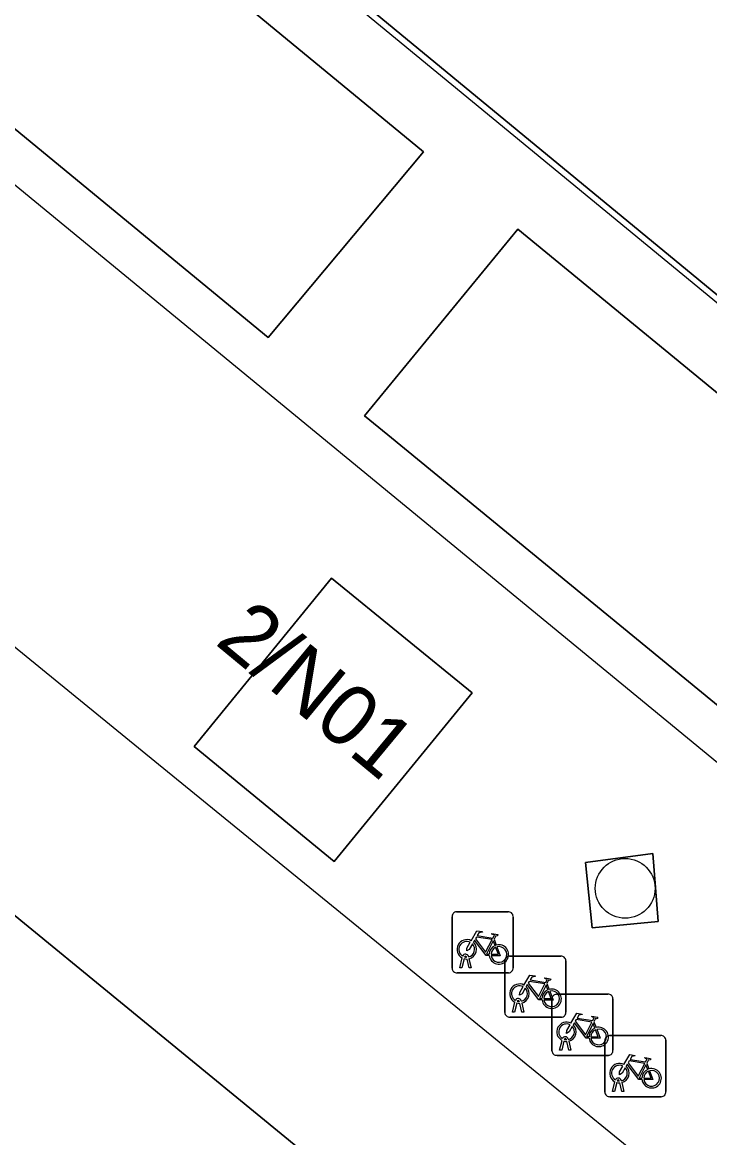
# Model space of a CAD drawing. Extents: x 161772 to 163126, y 383092 to 383917.
# Drawn here: x 161985.95 to 161997.2, y 383240.11 to 383258.37 of the extents above; entities that cross this region are included whole.
import ezdxf

# ---------------------------------------------------------------- set-up
doc = ezdxf.new("R2010")
doc.units = 0
for name, color, linetype in [('IMGEO_Boom', 7, 'Continuous'), ('IMGEO_Fietsenrek', 7, 'Continuous'), ('IMGEO_Groenvoorziening', 7, 'Continuous'), ('IMGEO_Lijnafwatering', 7, 'Continuous'), ('IMGEO_Pand', 7, 'Continuous'), ('IMGEO_Pand_nummerreeks', 7, 'Continuous'), ('IMGEO_Parkeervlak_gesloten', 7, 'Continuous'), ('IMGEO_Rijbaan_lokaal_open', 7, 'Continuous')]:
    doc.layers.add(name, color=color, linetype=linetype)

msp = doc.modelspace()

# ---------------------------------------------------------------- linework, layer by layer
at = {"layer": 'IMGEO_Boom'}
msp.add_circle((161995.818, 383244.188), 0.489, dxfattribs=at)
at = {"layer": 'IMGEO_Fietsenrek'}
for p, q in [((161993.059, 383243.805), (161993.9, 383243.805)), ((161993.9, 383243.805), (161993.059, 383243.805)), ((161993.984, 383243.73), (161993.984, 383242.889)), ((161993.984, 383242.889), (161993.984, 383243.73)), ((161992.984, 383242.88), (161992.984, 383243.721)), ((161992.984, 383243.721), (161992.984, 383242.88)), ((161993.671, 383243.354), (161993.707, 383243.259)), ((161993.111, 383242.889), (161993.15, 383243.049)), ((161993.18, 383243.037), (161993.145, 383242.889)), ((161993.222, 383243.061), (161993.221, 383243.065)), ((161993.263, 383242.889), (161993.229, 383243.031)), ((161993.253, 383243.072), (161993.254, 383243.065)), ((161993.261, 383243.035), (161993.296, 383242.889)), ((161993.923, 383243.079), (161994.764, 383243.079)), ((161994.764, 383243.079), (161993.923, 383243.079)), ((161994.848, 383243.004), (161994.848, 383242.163)), ((161994.848, 383242.163), (161994.848, 383243.004)), ((161993.145, 383242.889), (161993.111, 383242.889)), ((161993.296, 383242.889), (161993.263, 383242.889)), ((161993.848, 383242.154), (161993.848, 383242.995)), ((161993.848, 383242.995), (161993.848, 383242.154)), ((161993.909, 383242.805), (161993.068, 383242.805)), ((161993.068, 383242.805), (161993.909, 383242.805)), ((161994.535, 383242.628), (161994.571, 383242.533)), ((161994.693, 383242.454), (161995.534, 383242.454)), ((161995.534, 383242.454), (161994.693, 383242.454)), ((161993.975, 383242.163), (161994.014, 383242.323)), ((161994.044, 383242.311), (161994.009, 383242.163)), ((161994.086, 383242.335), (161994.085, 383242.339)), ((161994.127, 383242.163), (161994.093, 383242.305)), ((161994.117, 383242.346), (161994.118, 383242.339)), ((161994.125, 383242.309), (161994.16, 383242.163)), ((161994.618, 383241.529), (161994.618, 383242.37)), ((161994.618, 383242.37), (161994.618, 383241.529)), ((161995.618, 383242.379), (161995.618, 383241.538)), ((161995.618, 383241.538), (161995.618, 383242.379)), ((161994.009, 383242.163), (161993.975, 383242.163)), ((161994.16, 383242.163), (161994.127, 383242.163)), ((161994.773, 383242.079), (161993.932, 383242.079)), ((161993.932, 383242.079), (161994.773, 383242.079)), ((161995.305, 383242.003), (161995.341, 383241.908)), ((161994.887, 383241.721), (161994.888, 383241.714)), ((161995.559, 383241.777), (161996.4, 383241.777)), ((161996.4, 383241.777), (161995.559, 383241.777)), ((161994.745, 383241.538), (161994.784, 383241.698)), ((161994.779, 383241.538), (161994.745, 383241.538)), ((161994.814, 383241.686), (161994.779, 383241.538)), ((161994.856, 383241.71), (161994.855, 383241.714)), ((161994.897, 383241.538), (161994.863, 383241.68)), ((161994.895, 383241.684), (161994.93, 383241.538)), ((161994.93, 383241.538), (161994.897, 383241.538)), ((161995.484, 383240.852), (161995.484, 383241.693)), ((161995.484, 383241.693), (161995.484, 383240.852)), ((161996.484, 383241.702), (161996.484, 383240.861)), ((161996.484, 383240.861), (161996.484, 383241.702)), ((161995.543, 383241.454), (161994.702, 383241.454)), ((161994.702, 383241.454), (161995.543, 383241.454)), ((161996.171, 383241.326), (161996.207, 383241.231)), ((161995.611, 383240.861), (161995.65, 383241.021)), ((161995.68, 383241.009), (161995.645, 383240.861)), ((161995.722, 383241.033), (161995.721, 383241.037)), ((161995.763, 383240.861), (161995.729, 383241.003)), ((161995.753, 383241.044), (161995.754, 383241.037)), ((161995.761, 383241.007), (161995.796, 383240.861)), ((161995.645, 383240.861), (161995.611, 383240.861)), ((161995.796, 383240.861), (161995.763, 383240.861)), ((161996.409, 383240.777), (161995.568, 383240.777)), ((161995.568, 383240.777), (161996.409, 383240.777))]:
    msp.add_line(p, q, dxfattribs=at)
for points in [[(161993.297, 383243.331), (161993.392, 383243.495), (161993.478, 383243.481), (161993.48, 383243.472), (161993.424, 383243.461), (161993.397, 383243.416), (161993.653, 383243.375)], [(161993.64, 383243.35), (161993.383, 383243.391), (161993.366, 383243.362), (161993.533, 383243.142), (161993.64, 383243.35)], [(161993.653, 383243.375), (161993.678, 383243.424), (161993.672, 383243.428), (161993.649, 383243.432), (161993.637, 383243.439), (161993.636, 383243.442), (161993.638, 383243.447), (161993.733, 383243.432), (161993.735, 383243.422), (161993.725, 383243.409), (161993.713, 383243.403), (161993.699, 383243.409), (161993.671, 383243.354)], [(161993.318, 383243.279), (161993.266, 383243.189), (161993.226, 383243.164), (161993.227, 383243.211), (161993.282, 383243.305)], [(161993.593, 383243.087), (161993.543, 383243.087), (161993.352, 383243.338), (161993.333, 383243.306)], [(161993.688, 383243.252), (161993.658, 383243.329), (161993.549, 383243.111), (161993.592, 383243.111)], [(161993.622, 383243.111), (161993.742, 383243.11), (161993.698, 383243.224)], [(161993.718, 383243.231), (161993.773, 383243.086), (161993.623, 383243.086)], [(161994.161, 383242.605), (161994.256, 383242.769), (161994.342, 383242.755), (161994.344, 383242.746), (161994.288, 383242.735), (161994.261, 383242.69), (161994.517, 383242.649)], [(161994.504, 383242.624), (161994.247, 383242.665), (161994.23, 383242.636), (161994.397, 383242.416), (161994.504, 383242.624)], [(161994.517, 383242.649), (161994.542, 383242.698), (161994.536, 383242.702), (161994.513, 383242.706), (161994.501, 383242.713), (161994.5, 383242.716), (161994.502, 383242.721), (161994.597, 383242.706), (161994.599, 383242.696), (161994.589, 383242.683), (161994.577, 383242.677), (161994.563, 383242.683), (161994.535, 383242.628)], [(161994.182, 383242.553), (161994.13, 383242.463), (161994.09, 383242.438), (161994.091, 383242.485), (161994.146, 383242.579)], [(161994.457, 383242.361), (161994.407, 383242.361), (161994.216, 383242.612), (161994.197, 383242.58)], [(161994.552, 383242.526), (161994.522, 383242.603), (161994.413, 383242.385), (161994.456, 383242.385)], [(161994.486, 383242.385), (161994.606, 383242.384), (161994.562, 383242.498)], [(161994.582, 383242.505), (161994.637, 383242.36), (161994.487, 383242.36)], [(161994.931, 383241.98), (161995.026, 383242.144), (161995.112, 383242.13), (161995.114, 383242.121), (161995.058, 383242.11), (161995.031, 383242.065), (161995.287, 383242.024)], [(161995.287, 383242.024), (161995.312, 383242.073), (161995.306, 383242.077), (161995.283, 383242.081), (161995.271, 383242.088), (161995.27, 383242.091), (161995.272, 383242.096), (161995.367, 383242.081), (161995.369, 383242.071), (161995.359, 383242.058), (161995.347, 383242.052), (161995.333, 383242.058), (161995.305, 383242.003)], [(161994.952, 383241.928), (161994.9, 383241.838), (161994.86, 383241.813), (161994.861, 383241.86), (161994.916, 383241.954)], [(161995.227, 383241.736), (161995.177, 383241.736), (161994.986, 383241.987), (161994.967, 383241.955)], [(161995.274, 383241.999), (161995.017, 383242.04), (161995, 383242.011), (161995.167, 383241.791), (161995.274, 383241.999)], [(161995.322, 383241.901), (161995.292, 383241.978), (161995.183, 383241.76), (161995.226, 383241.76)], [(161995.256, 383241.76), (161995.376, 383241.759), (161995.332, 383241.873)], [(161995.352, 383241.88), (161995.407, 383241.735), (161995.257, 383241.735)], [(161995.797, 383241.303), (161995.892, 383241.467), (161995.978, 383241.453), (161995.98, 383241.444), (161995.924, 383241.433), (161995.897, 383241.388), (161996.153, 383241.347)], [(161996.14, 383241.322), (161995.883, 383241.363), (161995.866, 383241.334), (161996.033, 383241.114), (161996.14, 383241.322)], [(161996.153, 383241.347), (161996.178, 383241.396), (161996.172, 383241.4), (161996.149, 383241.404), (161996.137, 383241.411), (161996.136, 383241.414), (161996.138, 383241.419), (161996.233, 383241.404), (161996.235, 383241.394), (161996.225, 383241.381), (161996.213, 383241.375), (161996.199, 383241.381), (161996.171, 383241.326)], [(161995.818, 383241.251), (161995.766, 383241.161), (161995.726, 383241.136), (161995.727, 383241.183), (161995.782, 383241.277)], [(161996.093, 383241.059), (161996.043, 383241.059), (161995.852, 383241.31), (161995.833, 383241.278)], [(161996.188, 383241.224), (161996.158, 383241.301), (161996.049, 383241.083), (161996.092, 383241.083)], [(161996.122, 383241.083), (161996.242, 383241.082), (161996.198, 383241.196)], [(161996.218, 383241.203), (161996.273, 383241.058), (161996.123, 383241.058)]]:
    msp.add_lwpolyline(points, dxfattribs=at)
for centre, radius, start, end in [((161993.062, 383243.727), 0.0779, 92.4484, 184.2845), ((161993.062, 383243.727), 0.0779, 92.4484, 184.2845), ((161993.906, 383243.727), 0.0779, 2.4484, 94.2845), ((161993.906, 383243.727), 0.0779, 2.4484, 94.2845), ((161993.224, 383243.19), 0.159, 62.6766, 242.1369), ((161993.224, 383243.19), 0.129, 63.3192, 238.903), ((161993.224, 383243.19), 0.129, 283.6043, 43.4302), ((161993.224, 383243.19), 0.159, 283.5766, 46.6042), ((161993.751, 383243.106), 0.159, 113.3408, 178.3217), ((161993.751, 383243.106), 0.159, 187.0065, 105.7708), ((161993.751, 383243.106), 0.129, 113.923, 177.9556), ((161993.751, 383243.106), 0.129, 188.6715, 104.5883), ((161993.204, 383243.061), 0.0499, 12.8025, 158.6934), ((161993.224, 383243.19), 0.159, 253.9967, 271.7867), ((161993.204, 383243.061), 0.0174, 12.8025, 163.4502), ((161993.224, 383243.19), 0.129, 253.415, 269.0204), ((161993.926, 383243.001), 0.0779, 92.4484, 184.2845), ((161993.926, 383243.001), 0.0779, 92.4484, 184.2845), ((161994.77, 383243.001), 0.0779, 2.4484, 94.2845), ((161994.77, 383243.001), 0.0779, 2.4484, 94.2845), ((161993.062, 383242.883), 0.0779, 182.4484, 274.2845), ((161993.062, 383242.883), 0.0779, 182.4484, 274.2845), ((161993.906, 383242.883), 0.0779, 272.4484, 4.2845), ((161993.906, 383242.883), 0.0779, 272.4484, 4.2845), ((161994.088, 383242.464), 0.159, 62.6766, 242.1369), ((161994.088, 383242.464), 0.129, 63.3192, 238.903), ((161994.088, 383242.464), 0.129, 283.6043, 43.4302), ((161994.088, 383242.464), 0.159, 283.5766, 46.6042), ((161994.615, 383242.38), 0.159, 113.3408, 178.3217), ((161994.615, 383242.38), 0.159, 187.0065, 105.7708), ((161994.615, 383242.38), 0.129, 113.923, 177.9556), ((161994.615, 383242.38), 0.129, 188.6715, 104.5883), ((161994.696, 383242.376), 0.0779, 92.4484, 184.2845), ((161994.696, 383242.376), 0.0779, 92.4484, 184.2845), ((161995.54, 383242.376), 0.0779, 2.4484, 94.2845), ((161995.54, 383242.376), 0.0779, 2.4484, 94.2845), ((161994.068, 383242.335), 0.0499, 12.8025, 158.6934), ((161994.088, 383242.464), 0.159, 253.9967, 271.7867), ((161994.068, 383242.335), 0.0174, 12.8025, 163.4502), ((161994.088, 383242.464), 0.129, 253.415, 269.0204), ((161993.926, 383242.157), 0.0779, 182.4484, 274.2845), ((161993.926, 383242.157), 0.0779, 182.4484, 274.2845), ((161994.77, 383242.157), 0.0779, 272.4484, 4.2845), ((161994.77, 383242.157), 0.0779, 272.4484, 4.2845), ((161994.858, 383241.839), 0.159, 62.6766, 242.1369), ((161994.858, 383241.839), 0.129, 63.3192, 238.903), ((161994.858, 383241.839), 0.129, 283.6043, 43.4302), ((161994.858, 383241.839), 0.159, 283.5766, 46.6042), ((161995.385, 383241.755), 0.159, 187.0065, 105.7708), ((161994.838, 383241.71), 0.0499, 12.8025, 158.6934), ((161994.838, 383241.71), 0.0174, 12.8025, 163.4502), ((161995.385, 383241.755), 0.159, 113.3408, 178.3217), ((161995.385, 383241.755), 0.129, 113.923, 177.9556), ((161995.385, 383241.755), 0.129, 188.6715, 104.5883), ((161995.562, 383241.699), 0.0779, 92.4484, 184.2845), ((161995.562, 383241.699), 0.0779, 92.4484, 184.2845), ((161996.406, 383241.699), 0.0779, 2.4484, 94.2845), ((161996.406, 383241.699), 0.0779, 2.4484, 94.2845), ((161994.858, 383241.839), 0.159, 253.9967, 271.7867), ((161994.858, 383241.839), 0.129, 253.415, 269.0204), ((161995.54, 383241.532), 0.0779, 272.4484, 4.2845), ((161995.54, 383241.532), 0.0779, 272.4484, 4.2845), ((161994.696, 383241.532), 0.0779, 182.4484, 274.2845), ((161994.696, 383241.532), 0.0779, 182.4484, 274.2845), ((161995.724, 383241.162), 0.159, 62.6766, 242.1369), ((161995.724, 383241.162), 0.129, 63.3192, 238.903), ((161995.724, 383241.162), 0.129, 283.6043, 43.4302), ((161995.724, 383241.162), 0.159, 283.5766, 46.6042), ((161996.251, 383241.078), 0.159, 113.3408, 178.3217), ((161996.251, 383241.078), 0.159, 187.0065, 105.7708), ((161996.251, 383241.078), 0.129, 113.923, 177.9556), ((161996.251, 383241.078), 0.129, 188.6715, 104.5883), ((161995.704, 383241.033), 0.0499, 12.8025, 158.6934), ((161995.724, 383241.162), 0.159, 253.9967, 271.7867), ((161995.704, 383241.033), 0.0174, 12.8025, 163.4502), ((161995.724, 383241.162), 0.129, 253.415, 269.0204), ((161995.562, 383240.855), 0.0779, 182.4484, 274.2845), ((161995.562, 383240.855), 0.0779, 182.4484, 274.2845), ((161996.406, 383240.855), 0.0779, 272.4484, 4.2845), ((161996.406, 383240.855), 0.0779, 272.4484, 4.2845)]:
    msp.add_arc(centre, radius, start, end, dxfattribs=at)
at = {"layer": 'IMGEO_Groenvoorziening'}
msp.add_lwpolyline([(161995.168, 383244.614), (161995.275, 383243.543), (161996.358, 383243.645), (161996.268, 383244.758)], close=True, dxfattribs=at)
at = {"layer": 'IMGEO_Lijnafwatering'}
for points in [[(161982.984, 383265.577), (161997.1, 383253.959)], [(161974.243, 383265.241), (161989.193, 383252.942)], [(161988.122, 383246.267), (161973.639, 383258.081)], [(161997.1, 383253.959), (162011.215, 383242.341)], [(161989.193, 383252.942), (162004.142, 383240.642)], [(162002.606, 383234.454), (161988.122, 383246.267)]]:
    msp.add_lwpolyline(points, dxfattribs=at)
at = {"layer": 'IMGEO_Pand'}
msp.add_lwpolyline([(162035.261, 383203.214), (161971.077, 383255.833), (161951.971, 383232.387), (161952.136, 383232.253), (161952.475, 383232.671), (161953.27, 383232.025), (161952.93, 383231.606), (161961.717, 383224.452), (161963.556, 383222.955), (161966.982, 383220.165), (161968.9, 383218.604), (161976.432, 383212.471), (161978.338, 383210.919), (161981.311, 383208.499), (161983.245, 383206.925), (161993.99, 383198.176), (161995.826, 383196.682), (161998.749, 383194.301)], dxfattribs=at)
msp.add_lwpolyline([(161988.764, 383246.512), (161991.055, 383244.629), (161993.311, 383247.391), (161991.01, 383249.265)], close=True, dxfattribs=at)
at = {"layer": 'IMGEO_Parkeervlak_gesloten'}
for points in [[(161992.515, 383256.248), (161977.196, 383268.872), (161974.671, 383265.816), (161989.977, 383253.21)], [(161994.063, 383254.984), (161991.551, 383251.928), (161991.934, 383251.613), (161992.962, 383250.769), (162003.025, 383242.509), (162005.54, 383245.553)]]:
    msp.add_lwpolyline(points, close=True, dxfattribs=at)
at = {"layer": 'IMGEO_Rijbaan_lokaal_open'}
for points in [[(161982.816, 383272.991), (161980.385, 383274.991), (161956.7, 383294.535), (161953.358, 383290.171), (161965.539, 383280.118), (161976.98, 383270.676), (162068.256, 383195.442), (162072.024, 383199.58), (162068.652, 383202.355), (162022.469, 383240.368), (162022.186, 383240.601)], [(161989.977, 383253.21), (161974.671, 383265.816), (161977.196, 383268.872), (161992.515, 383256.248)], [(162003.025, 383242.509), (161992.962, 383250.769), (161991.934, 383251.613), (161991.551, 383251.928), (161994.063, 383254.984), (162005.54, 383245.553)], [(161988.764, 383246.512), (161991.01, 383249.265), (161993.311, 383247.391), (161991.055, 383244.629)], [(161995.275, 383243.543), (161995.168, 383244.614), (161996.268, 383244.758), (161996.358, 383243.645)]]:
    msp.add_lwpolyline(points, close=True, dxfattribs=at)
msp.add_lwpolyline([(162054.895, 383187.865), (162058.675, 383184.763), (162059.171, 383185.317), (162057.611, 383186.767), (162058.979, 383188.263), (162060.56, 383186.888), (162066.195, 383193.13), (162067.57, 383194.688), (162068.256, 383195.442), (161976.98, 383270.676), (161965.539, 383280.118), (161962.128, 383275.94), (161955.86, 383268.264), (161962.269, 383262.995), (161962.168, 383262.726), (161966.806, 383258.778), (161967.104, 383258.925), (161971.077, 383255.833), (162035.261, 383203.214), (162035.951, 383202.874)], dxfattribs=at)

# ---------------------------------------------------------------- texts
at = {"layer": 'IMGEO_Pand_nummerreeks'}
msp.add_text('2/N01', height=1, rotation=320.3857, dxfattribs=at).set_placement((161989.085, 383248.201))

doc.saveas('drawing.dxf')
